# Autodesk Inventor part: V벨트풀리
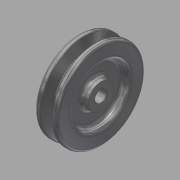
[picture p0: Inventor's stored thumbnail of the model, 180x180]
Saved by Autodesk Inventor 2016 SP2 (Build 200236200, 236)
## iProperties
Created: 2015-11
Part Number: V벨트풀리
Material: 강철, 탄소
Document SubType Name: Modeling
Designer: mduedu
Density: 1 g/cm^3
Appearance: 반광택
Author: mduedu
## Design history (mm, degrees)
sketch "스케치1"
  geometry: L1 (-9.5, 0)-(9.5, 0); L2 (0, 0)-(0, 37.7); L3 (-4.825, 37.7)-(-9.5, 37.7); L4 (-9.5, 37.7)-(-9.5, 0); L5 (0, 28.7)-(-2.074, 28.7); L6 (-2.074, 28.7)-(-4.825, 37.7); L7 (4.825, 37.7)-(9.5, 37.7); L8 (9.5, 37.7)-(9.5, 0); L9 (0, 28.7)-(2.074, 28.7); L10 (2.074, 28.7)-(4.825, 37.7); L11 (-9.5, 35)-(9.5, 35); 3 further points
  constraints: 22 end point, 7 point on line, 4 perpendicular, 3 symmetric about line, 1 coincident, 1 horizontal, 1 horizontal alignment, 1 midpoint, 1 vertical
  dimensions: "d0" = 19 distance of L1.start L1.end; "d2" = 75.4 diameter of L2.end L1 (derived); "d3" = 34 deg angle of L10 L6; "d4" = 6.3 distance between parallel lines of L11 L9; "d5" = 2.7 distance between parallel lines of L7 L11; "d6" = 8 distance of point (4, 35) point (-4, 35); "d7" = 70 diameter of L11 L1
revolve "회전1" sketch "스케치1" stored, may be unused: angle "d8" = 90 deg
sketch "스케치2"
  geometry: C1 r 24 at (0, 0); C2 r 11 at (0, 0); 1 further point
  constraints: 2 centre point, 2 coincident
  dimensions: "d9" = 48 diameter of C1; "d10" = 22 diameter of C2
extrude "돌출1" cut sketch "스케치2" distance "d11" = 6; taper "d12" = 0 deg
fillet "모깎기1" dims "d13" = 3
fillet "모깎기2" dims "d14" = 3
fillet "모깎기3" dims "d15" = 1, "d16" = 0.5, "d17" = 2
hole "구멍1" diameter "d20" = 10; stored, may be unused: countersink angle "d24" = 90 deg, drill point angle "d26" = 118 deg; dims "d18" = 10, "d19" = 10, "d21" = 6, "d22" = 4, "d23" = 2, "d25" = 8
sketch "스케치3"
  geometry: L1 (-1.5, 0)-(1.5, 0); L2 (1.5, 0)-(1.5, 6.4); L3 (1.5, 6.4)-(-1.5, 6.4); L4 (-1.5, 6.4)-(-1.5, 0); 2 further points
  constraints: 8 end point, 2 parallel, 1 coincident, 1 horizontal, 1 midpoint, 1 perpendicular
  dimensions: "d27" = 3 distance of L2.end L3.end; "d29" = 6.4 distance of L3.end L1.start
extrude "돌출2" cut sketch "스케치3" stored distance "d30" = 6; taper "d31" = 0 deg
chamfer "모따기1" distance "d32" = 0.5; stored, may be unused: second distance "d33" = 2, angle "d34" = 45 deg
node "솔리드1"
mirror "대칭1"
